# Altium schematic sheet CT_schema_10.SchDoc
size 742 x 377 mm
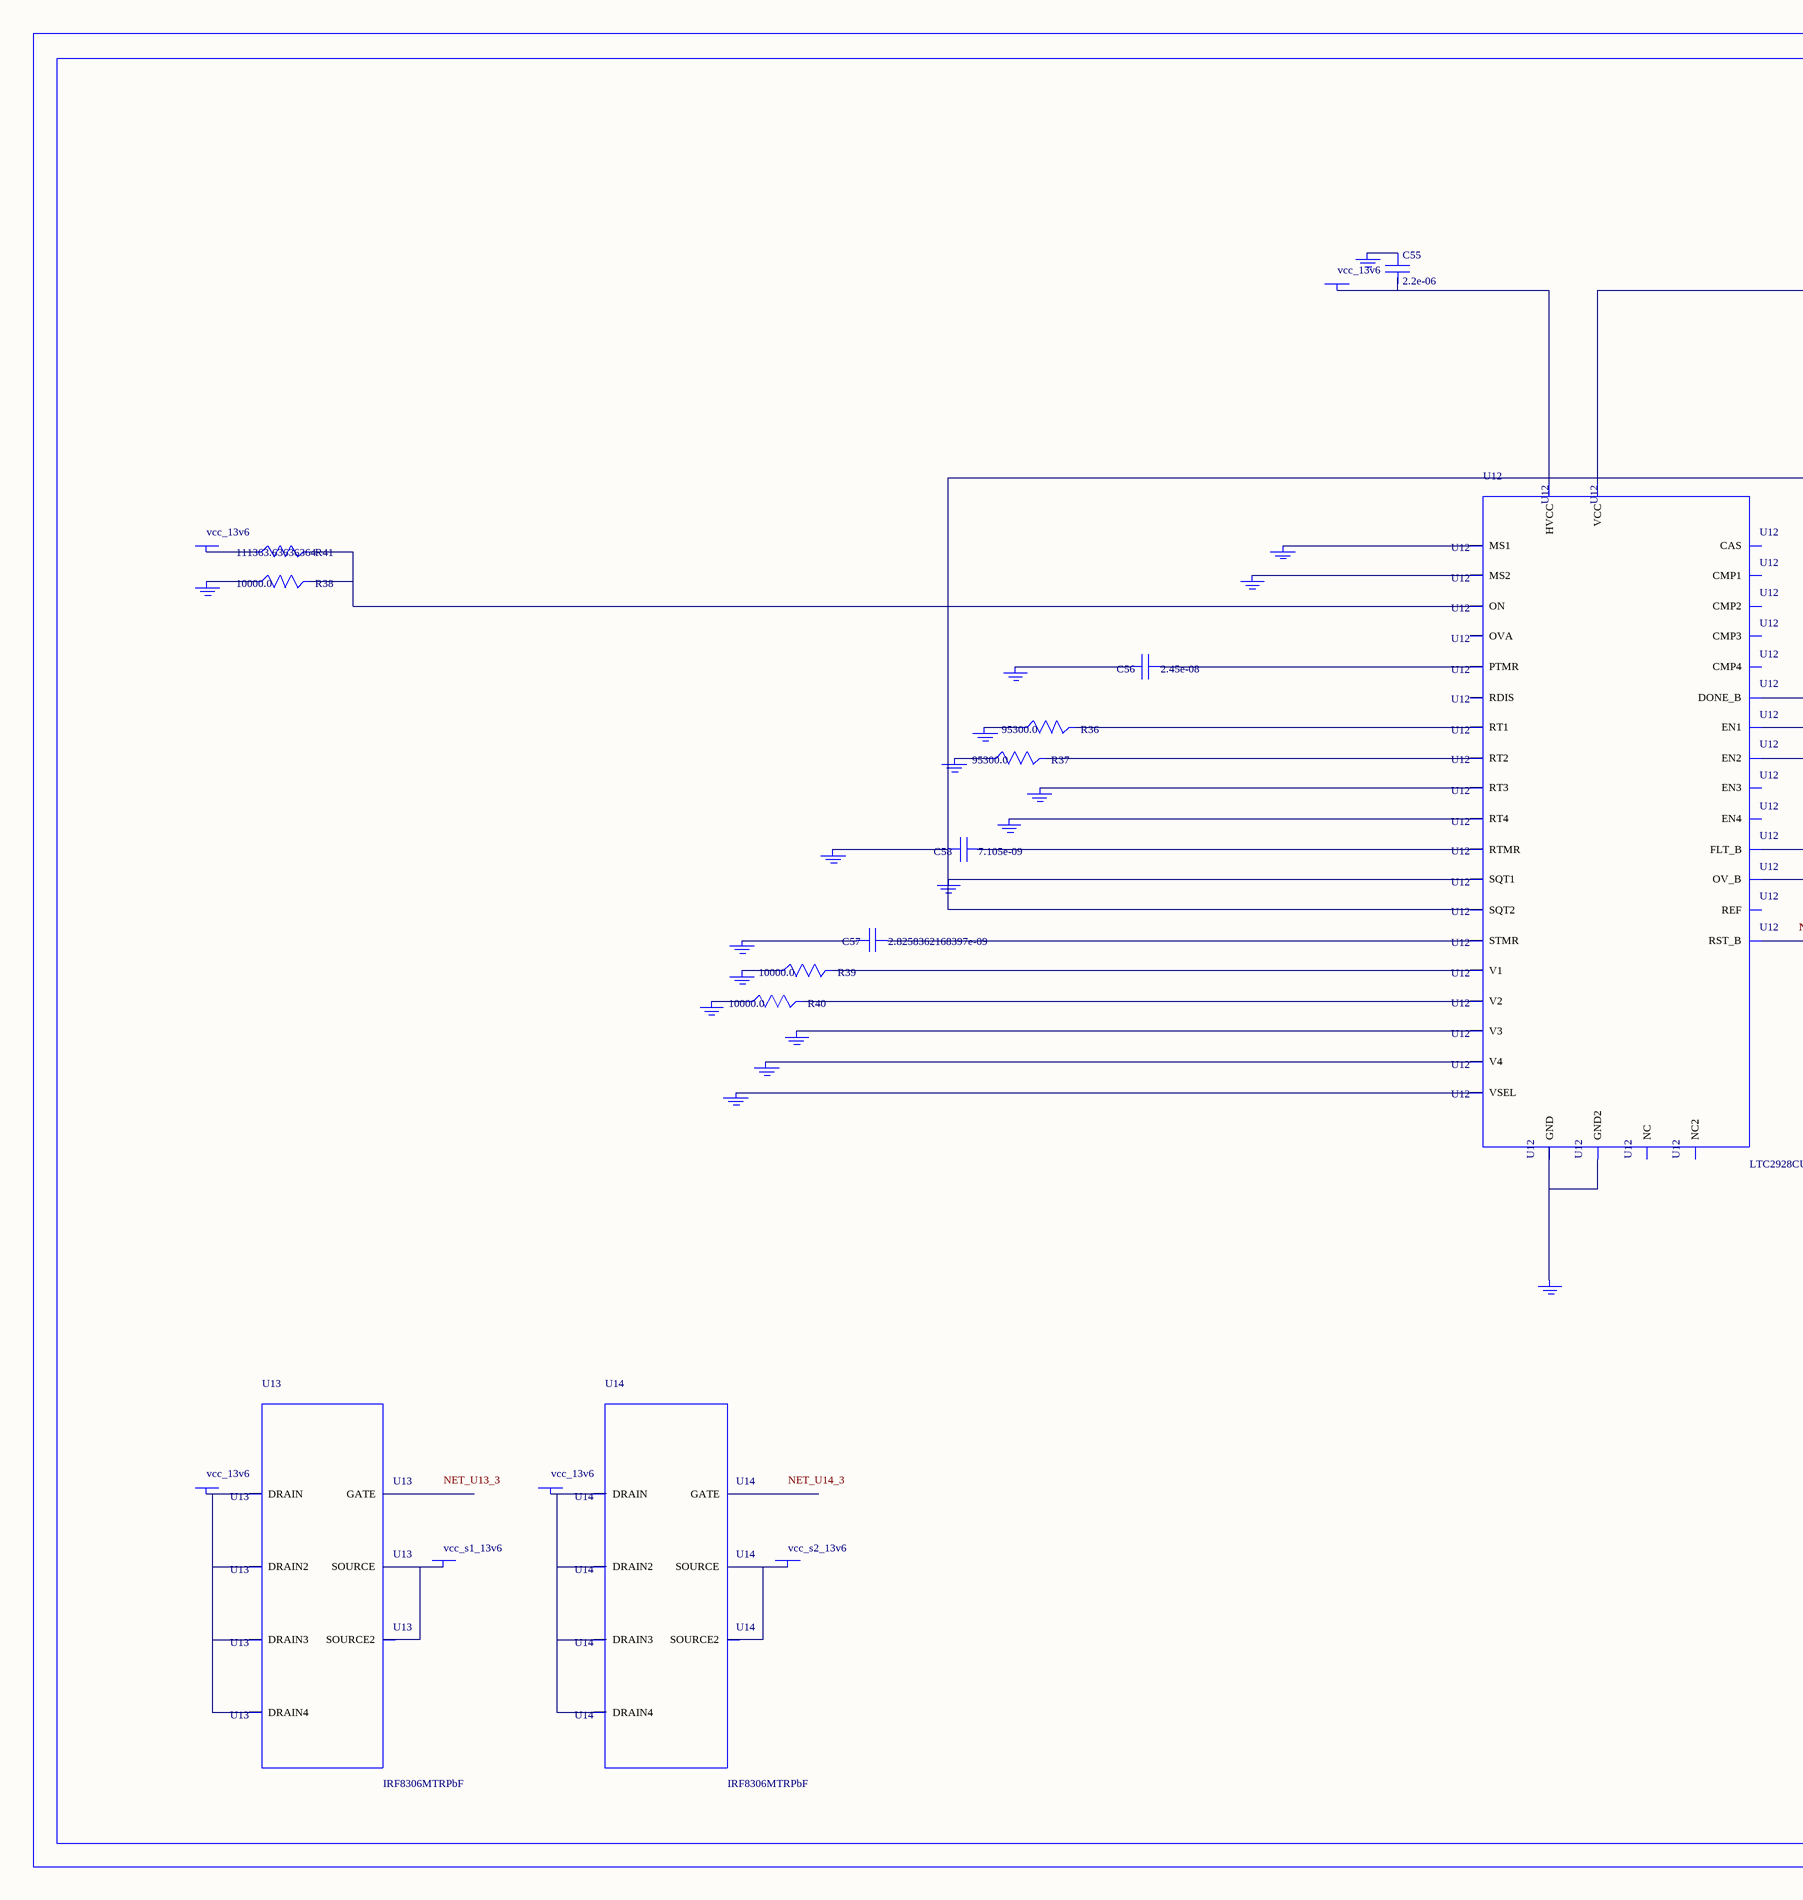
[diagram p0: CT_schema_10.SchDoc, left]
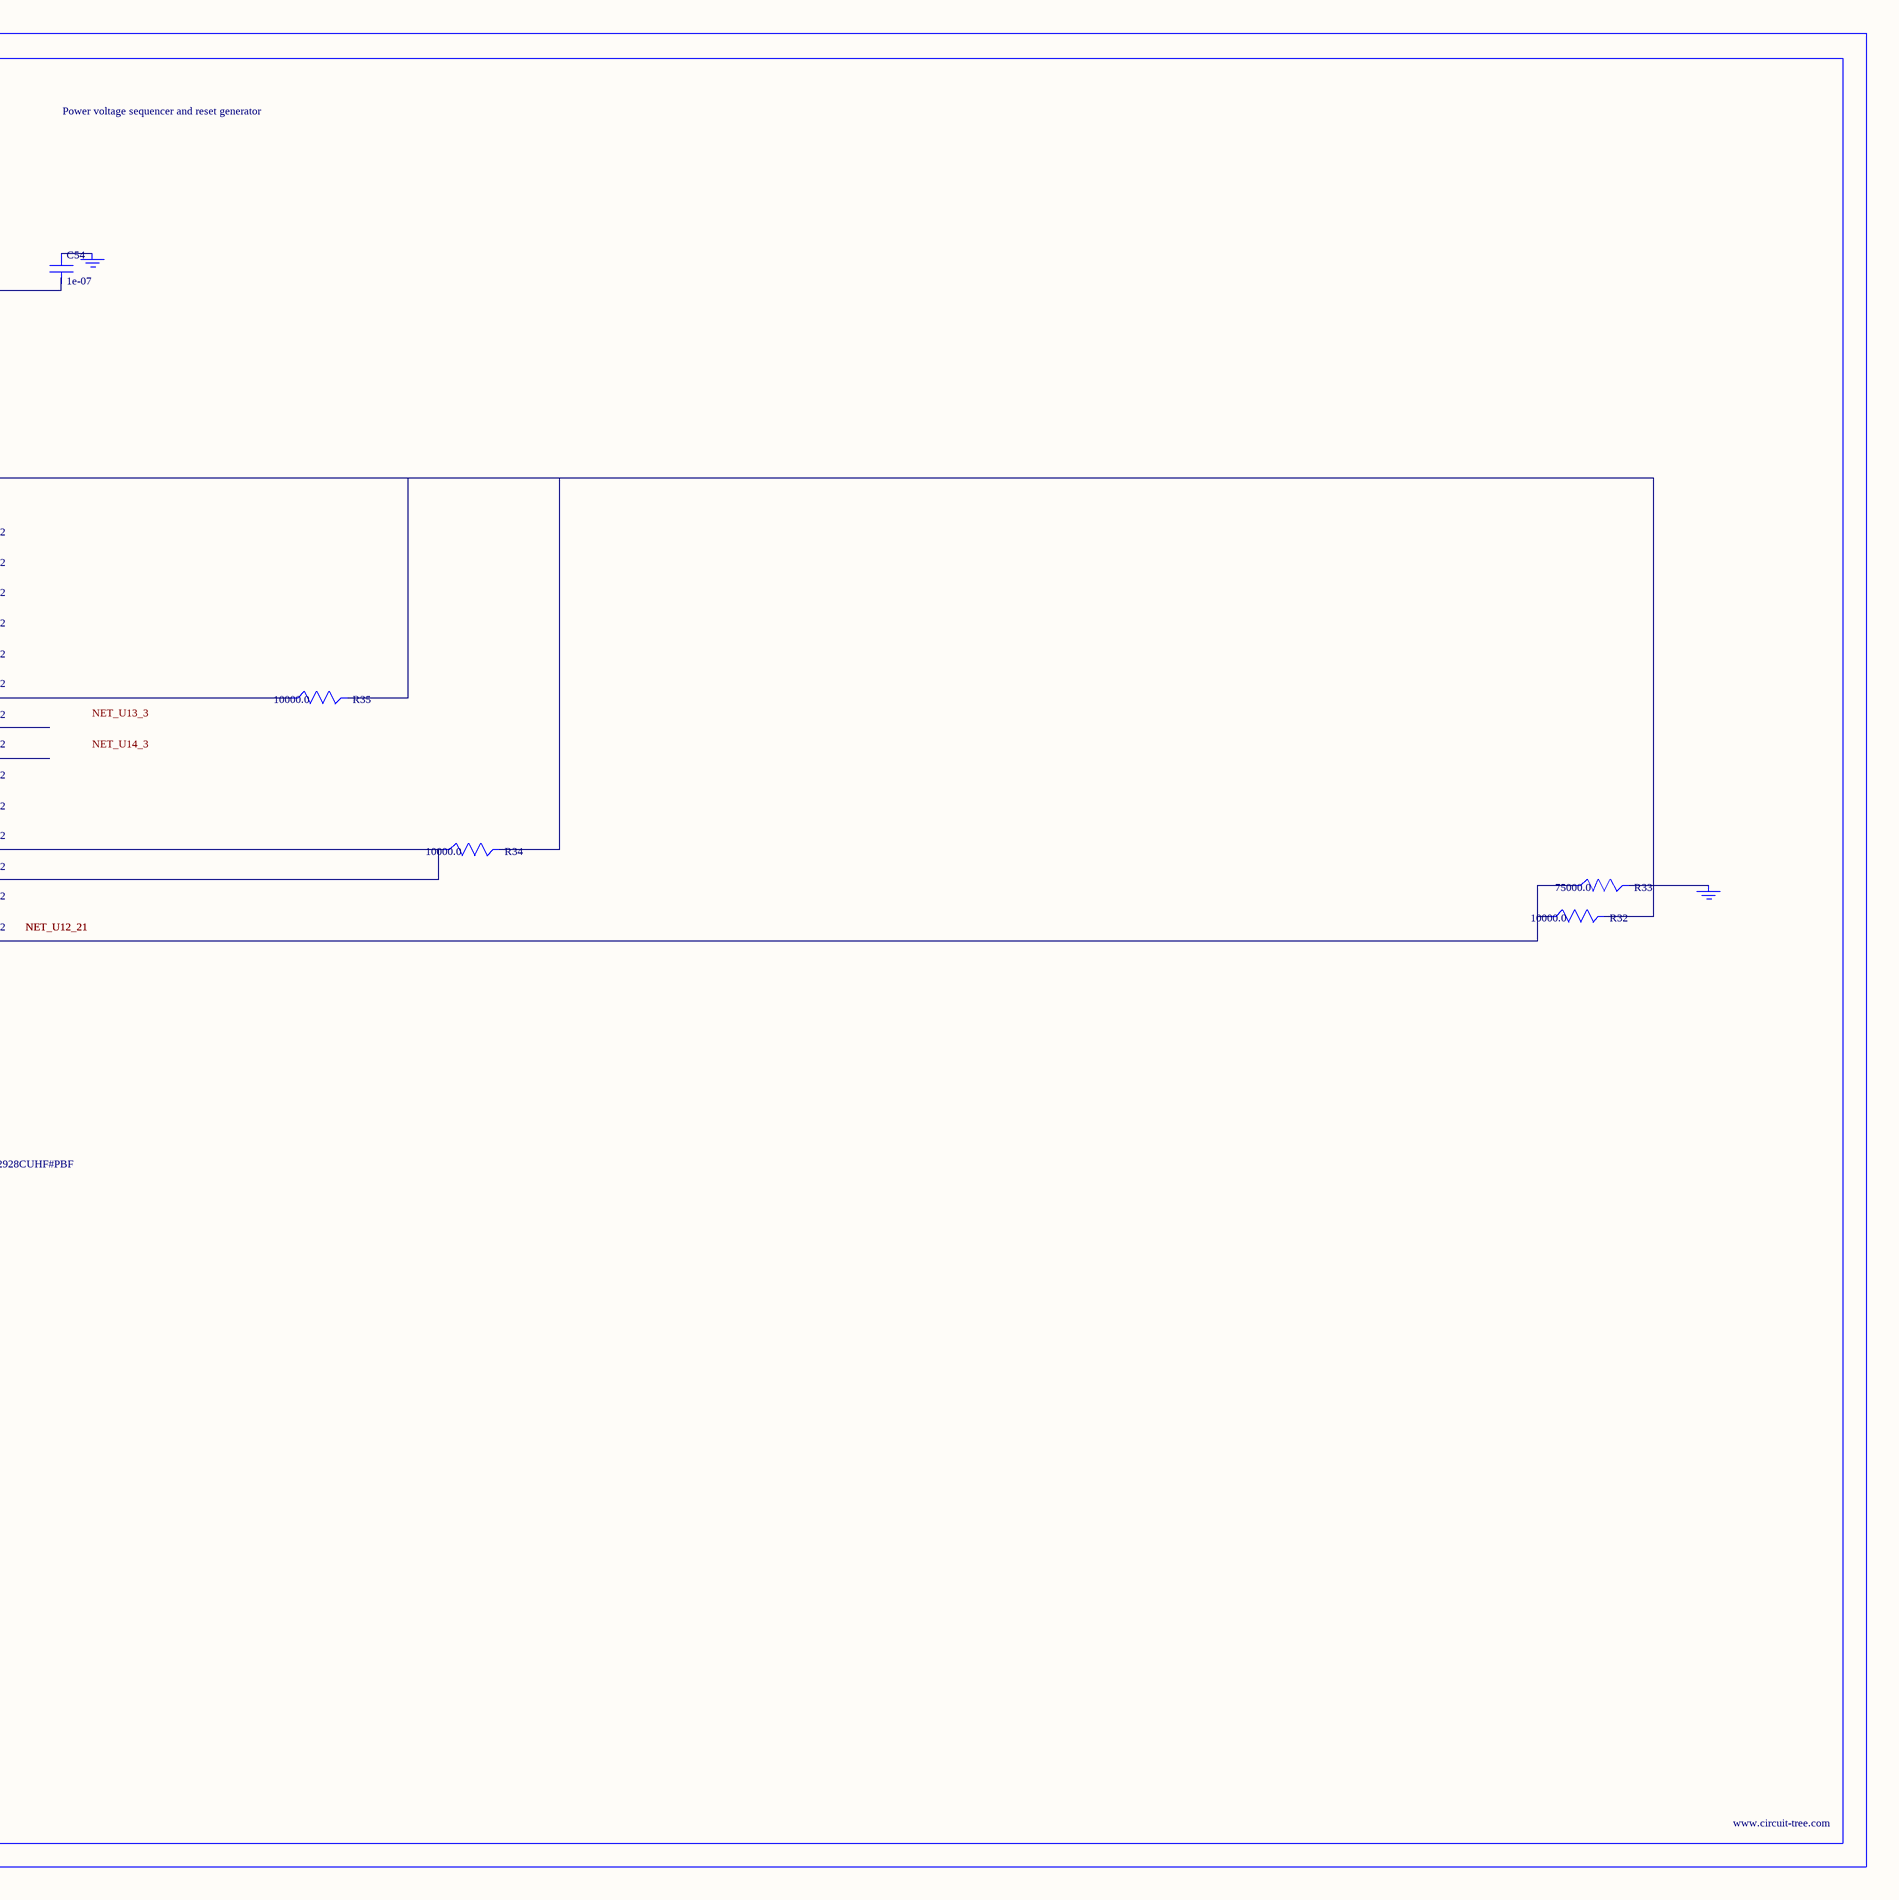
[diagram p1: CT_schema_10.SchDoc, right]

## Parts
BORDER9  (no value)
C54  1e-07  [C0402]
C55  2.2e-06  [C0603]
C56  2.45e-08  [R0603]
C57  2.8258362168397e-09  [R0603]
C58  7.105e-09  [R0603]
GND_INSTANCE_9_0  (no value)
GND_INSTANCE_9_1  (no value)
GND_INSTANCE_9_2  (no value)
GND_INSTANCE_9_3  (no value)
GND_INSTANCE_9_4  (no value)
GND_INSTANCE_9_5  (no value)
GND_INSTANCE_9_6  (no value)
GND_INSTANCE_9_7  (no value)
GND_INSTANCE_9_8  (no value)
GND_INSTANCE_9_9  (no value)
GND_INSTANCE_9_10  (no value)
GND_INSTANCE_9_11  (no value)
GND_INSTANCE_9_12  (no value)
GND_INSTANCE_9_13  (no value)
GND_INSTANCE_9_14  (no value)
GND_INSTANCE_9_15  (no value)
GND_INSTANCE_9_16  (no value)
GND_INSTANCE_9_17  (no value)
GND_INSTANCE_9_18  (no value)
GND_INSTANCE_9_19  (no value)
POWER_INSTANCE_9_0  vcc_13v6
POWER_INSTANCE_9_1  vcc_13v6
POWER_INSTANCE_9_2  vcc_13v6
POWER_INSTANCE_9_3  vcc_s1_13v6
POWER_INSTANCE_9_4  vcc_13v6
POWER_INSTANCE_9_5  vcc_s2_13v6
R32  10000.0  [R0603]
R33  75000.0  [R0603]
R34  10000.0  [R0603]
R35  10000.0  [R0603]
R36  95300.0  [R0603]
R37  95300.0  [R0603]
R38  10000.0  [R0603]
R39  10000.0  [R0603]
R40  10000.0  [R0603]
R41  111363.63636364  [R0603]
U12  LTC2928CUHF#PBF  [QFN-38_UHF]
U13  IRF8306MTRPbF  [IRF8306MTRPBF]
U14  IRF8306MTRPbF  [IRF8306MTRPBF]

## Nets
NetC54_1: C54.1 GND_INSTANCE_9_10.0(GND)
NetC54_2: C54.2 C58.2 GND_INSTANCE_9_5.0(GND) GND_INSTANCE_9_15.0(GND) R32.2 R34.2 R35.2 U12.10(SQT1) U12.11(SQT2) U12.22(VCC)
NetC55_1: C55.1 GND_INSTANCE_9_11.0(GND)
NetC55_2: C55.2 POWER_INSTANCE_9_1.0(PWR) U12.23(HVCC)
NetC56_1: C56.1 U12.27(PTMR)
NetC56_2: C56.2 GND_INSTANCE_9_14.0(GND)
NetC57_1: C57.1 U12.26(STMR)
NetC57_2: C57.2 GND_INSTANCE_9_13.0(GND)
NetC58_1: C58.1 U12.28(RTMR)
NetGND_INSTANCE_9_0_0: GND_INSTANCE_9_0.0(GND) R39.1
NetGND_INSTANCE_9_1_0: GND_INSTANCE_9_1.0(GND) R36.1
NetGND_INSTANCE_9_2_0: GND_INSTANCE_9_2.0(GND) R37.1
NetGND_INSTANCE_9_3_0: GND_INSTANCE_9_3.0(GND) U12.8(RT3)
NetGND_INSTANCE_9_4_0: GND_INSTANCE_9_4.0(GND) U12.9(RT4)
NetGND_INSTANCE_9_6_0: GND_INSTANCE_9_6.0(GND) U12.12(MS1)
NetGND_INSTANCE_9_7_0: GND_INSTANCE_9_7.0(GND) U12.13(MS2)
NetGND_INSTANCE_9_8_0: GND_INSTANCE_9_8.0(GND) R38.1
NetGND_INSTANCE_9_9_0: GND_INSTANCE_9_9.0(GND) R33.2
NetGND_INSTANCE_9_12_0: GND_INSTANCE_9_12.0(GND) U12.25(VSEL)
NetGND_INSTANCE_9_16_0: GND_INSTANCE_9_16.0(GND) U12.30(V4)
NetGND_INSTANCE_9_17_0: GND_INSTANCE_9_17.0(GND) U12.32(V3)
NetGND_INSTANCE_9_18_0: GND_INSTANCE_9_18.0(GND) R40.1
NetGND_INSTANCE_9_19_0: GND_INSTANCE_9_19.0(GND) U12.24(GND) U12.39(GND2)
NetPOWER_INSTANCE_9_0_0: POWER_INSTANCE_9_0.0(PWR) R41.1
NetPOWER_INSTANCE_9_2_0: POWER_INSTANCE_9_2.0(PWR) U13.1(DRAIN) U13.2(DRAIN2) U13.6(DRAIN3) U13.7(DRAIN4)
NetPOWER_INSTANCE_9_3_0: POWER_INSTANCE_9_3.0(PWR) U13.4(SOURCE) U13.5(SOURCE2)
NetPOWER_INSTANCE_9_4_0: POWER_INSTANCE_9_4.0(PWR) U14.1(DRAIN) U14.2(DRAIN2) U14.6(DRAIN3) U14.7(DRAIN4)
NetPOWER_INSTANCE_9_5_0: POWER_INSTANCE_9_5.0(PWR) U14.4(SOURCE) U14.5(SOURCE2)
NetR32_1: R32.1 R33.1 U12.21(RST_B)
NetR34_1: R34.1 U12.19(FLT_B) U12.20(OV_B)
NetR35_1: R35.1 U12.18(DONE_B)
NetR36_2: R36.2 U12.6(RT1)
NetR37_2: R37.2 U12.7(RT2)
NetR38_2: R38.2 R41.2 U12.16(ON)
NetR39_2: R39.2 U12.3(V1)
NetR40_2: R40.2 U12.38(V2)

Not connected (* = marked no-connect by the designer): U12 1(OVA) 2(EN1) 4(NC) 5(REF) 14(RDIS) 15(CAS) 17(NC2) 29(EN4) 31(EN3) 33(CMP3) 34(CMP4) 35(CMP1) 36(CMP2) 37(EN2); U13 3(GATE); U14 3(GATE)

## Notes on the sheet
- Labels drawn without touching a wire or pin: NET_U13_3, NET_U14_3

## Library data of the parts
BORDER9 = BORDER_PAGE9
C54 = C0402C104K3RACTU
C55 = GRM188R61H225KE1115D
C56 = C56
C57 = C57
C58 = C58
GND_INSTANCE_9_0-GND_INSTANCE_9_19 = GND
POWER_INSTANCE_9_0-POWER_INSTANCE_9_5 = PWR
R32 R34 R35 R38-R40 = RC0603JR-0710KL
R33 = RC0603JR-0775KL
R36 R37 = RC0603FR-0795K3L
R41 = R41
